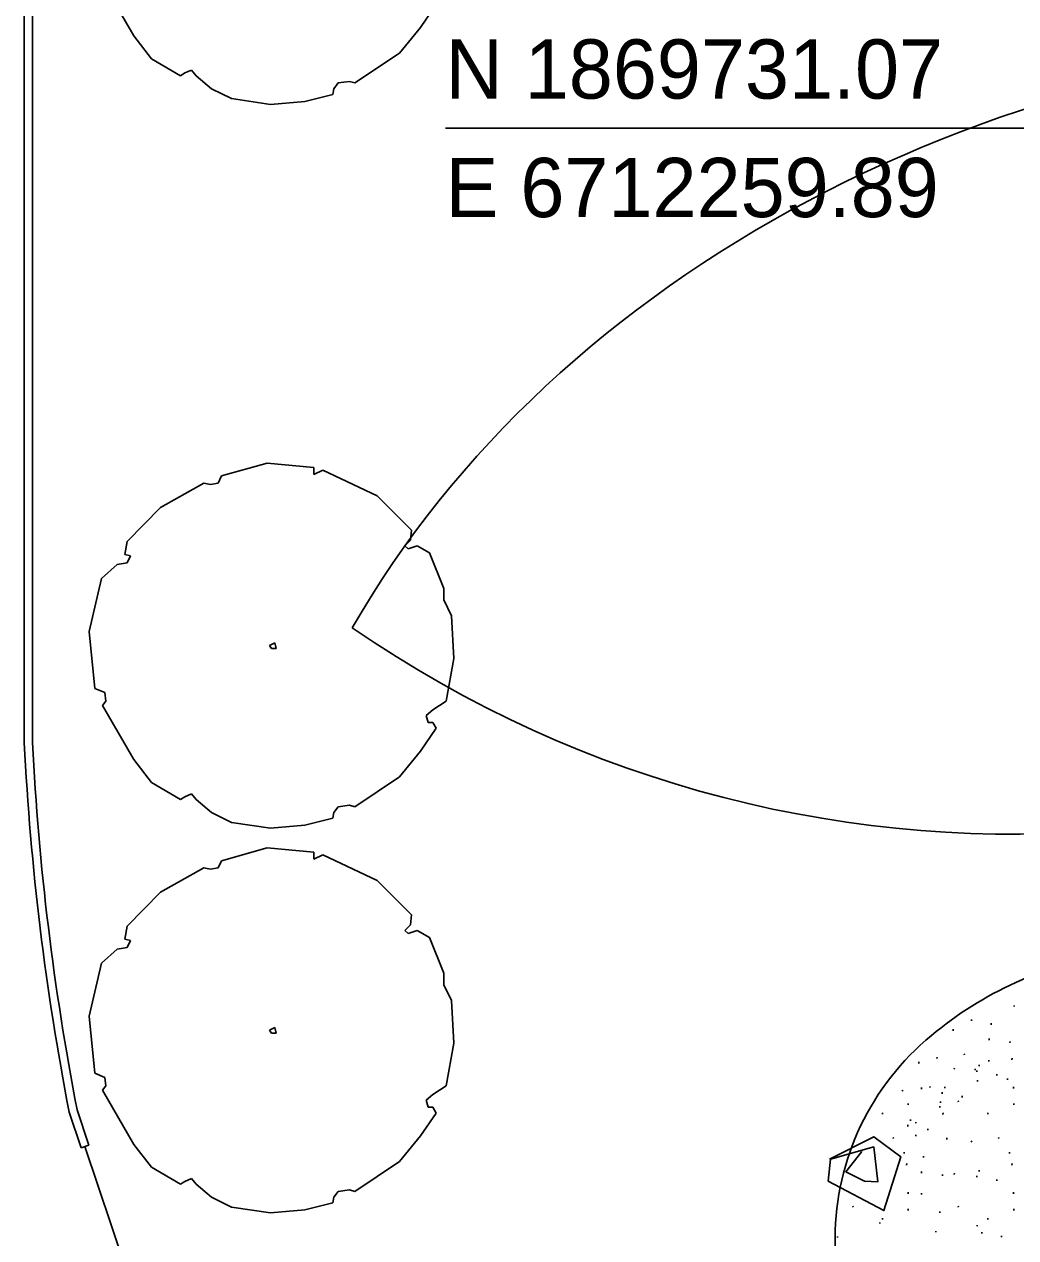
# Model space of a CAD drawing. Extents: x 6712138 to 6712574, y 1869536 to 1870160.
# Drawn here: x 6712188 to 6712248.3, y 1869628.3 to 1869702.1 of the extents above; entities that cross this region are included whole.
import ezdxf

# ---------------------------------------------------------------- set-up
doc = ezdxf.new("R2010")
doc.units = 0
for name, color, linetype in [('A-FLOR-PATT', 7, 'Continuous'), ('A-WALL', 7, 'Continuous'), ('C-PRKG-CONC', 7, 'Continuous'), ('I-WALL', 7, 'Continuous'), ('L-tree', 7, 'Continuous'), ('P-SANR-FIXT', 7, 'Continuous')]:
    doc.layers.add(name, color=color, linetype=linetype)

# ---------------------------------------------------------------- blocks, each defined once
blk = doc.blocks.new('TREE 1')
at = {"layer": 'L-tree'}
for p, q in [((-0.0275, 0.572), (-0.1682, 0.5324)), ((0.1167, 0.5588), (-0.0275, 0.572)), ((-0.1682, 0.5324), (-0.1785, 0.5104)), ((0.1167, 0.5368), (0.1167, 0.5588)), ((0.1441, 0.55), (0.1167, 0.5368)), ((0.3123, 0.4708), (0.1441, 0.55)), ((-0.2231, 0.5104), (-0.357, 0.4356)), ((-0.2025, 0.506), (-0.2231, 0.5104)), ((-0.1785, 0.5104), (-0.2025, 0.506)), ((0.4187, 0.3652), (0.3123, 0.4708)), ((-0.357, 0.4356), (-0.4599, 0.33)), ((0.4153, 0.3344), (0.4187, 0.3652)), ((-0.4599, 0.33), (-0.4668, 0.2904)), ((0.3981, 0.3168), (0.4153, 0.3344)), ((0.4084, 0.308), (0.3981, 0.3168)), ((0.4359, 0.3168), (0.4084, 0.308)), ((0.4737, 0.2948), (0.4359, 0.3168)), ((-0.4599, 0.264), (-0.4908, 0.2596)), ((-0.4668, 0.2904), (-0.4496, 0.286)), ((-0.4496, 0.286), (-0.4599, 0.264)), ((0.5183, 0.1848), (0.4737, 0.2948)), ((-0.4908, 0.2596), (-0.5389, 0.2156)), ((-0.5389, 0.2156), (-0.5766, 0.0528)), ((0.5183, 0.1496), (0.5183, 0.1848)), ((0.5423, 0.1012), (0.5183, 0.1496)), ((0.5492, -0.0308), (0.5423, 0.1012)), ((-0.5766, 0.0528), (-0.5595, -0.1232)), ((-0.0034, 0.0176), (-0.0206, 0.0088)), ((-0.0206, 0.0088), (-0.0137, 0)), ((-0.0137, 0), (0, 0)), ((0, 0), (-0.0034, 0.0176)), ((0.5251, -0.1628), (0.5492, -0.0308)), ((-0.5595, -0.1232), (-0.5286, -0.1364)), ((-0.5286, -0.1364), (-0.5251, -0.1628)), ((-0.5251, -0.1628), (-0.5354, -0.176)), ((-0.5354, -0.176), (-0.4393, -0.3432)), ((0.4839, -0.1892), (0.5251, -0.1628)), ((0.4634, -0.2068), (0.4839, -0.1892)), ((0.4702, -0.2288), (0.4634, -0.2068)), ((0.4462, -0.3168), (0.4942, -0.2464)), ((0.4839, -0.2288), (0.4702, -0.2288)), ((0.4942, -0.2464), (0.4839, -0.2288)), ((0.381, -0.396), (0.4462, -0.3168)), ((-0.4393, -0.3432), (-0.3844, -0.4136)), ((0.2437, -0.4884), (0.381, -0.396)), ((-0.3844, -0.4136), (-0.2952, -0.4664)), ((-0.2815, -0.4576), (-0.2609, -0.4488)), ((-0.2609, -0.4488), (-0.2471, -0.4664)), ((-0.2952, -0.4664), (-0.2815, -0.4576)), ((-0.2471, -0.4664), (-0.1991, -0.506)), ((0.1922, -0.4884), (0.2265, -0.484)), ((0.2265, -0.484), (0.2437, -0.4884)), ((-0.1991, -0.506), (-0.1373, -0.5368)), ((0.0892, -0.5456), (0.175, -0.5236)), ((0.175, -0.5236), (0.1785, -0.506)), ((0.1785, -0.506), (0.1922, -0.4884)), ((-0.1373, -0.5368), (-0.0172, -0.5544)), ((-0.0172, -0.5544), (0.0892, -0.5456))]:
    blk.add_line(p, q, dxfattribs=at)

msp = doc.modelspace()

# ---------------------------------------------------------------- linework, layer by layer
at = {"layer": 'A-FLOR-PATT'}
for p, q in [((6712248.165, 1869642.384), (6712248.165, 1869642.442)), ((6712245.574, 1869641.524), (6712245.574, 1869641.591)), ((6712246.762, 1869641.284), (6712246.762, 1869641.367)), ((6712244.464, 1869640.917), (6712244.464, 1869641.004)), ((6712246.642, 1869640.341), (6712246.642, 1869640.434)), ((6712247.902, 1869640.184), (6712247.911, 1869640.258)), ((6712242.372, 1869638.93), (6712242.372, 1869639.016)), ((6712243.453, 1869639.227), (6712243.49, 1869639.301)), ((6712245.147, 1869639.447), (6712245.12, 1869639.511)), ((6712246.628, 1869639.047), (6712246.628, 1869639.131)), ((6712248.016, 1869639.154), (6712248.033, 1869639.247)), ((6712244.519, 1869638.584), (6712244.527, 1869638.646)), ((6712245.784, 1869638.521), (6712245.784, 1869638.607)), ((6712245.889, 1869638.421), (6712245.889, 1869638.507)), ((6712246.042, 1869638.761), (6712246.042, 1869638.844)), ((6712247.102, 1869638.194), (6712247.102, 1869638.281)), ((6712242.525, 1869637.374), (6712242.525, 1869637.458)), ((6712243.055, 1869637.459), (6712243.028, 1869637.523)), ((6712243.95, 1869637.431), (6712243.95, 1869637.514)), ((6712245.924, 1869637.824), (6712245.94, 1869637.917)), ((6712247.748, 1869637.924), (6712247.748, 1869638.011)), ((6712248.125, 1869637.414), (6712248.125, 1869637.507)), ((6712241.361, 1869637.239), (6712241.398, 1869637.313)), ((6712243.796, 1869637.091), (6712243.796, 1869637.177)), ((6712245.01, 1869636.864), (6712245.01, 1869636.951)), ((6712241.729, 1869636.404), (6712241.729, 1869636.49)), ((6712243.645, 1869636.25), (6712243.645, 1869636.338)), ((6712243.692, 1869636.533), (6712243.692, 1869636.619)), ((6712244.785, 1869636.601), (6712244.756, 1869636.664)), ((6712248.133, 1869636.404), (6712248.133, 1869636.49)), ((6712240.152, 1869635.844), (6712240.152, 1869635.93)), ((6712241.858, 1869635.443), (6712241.858, 1869635.527)), ((6712242.189, 1869635.29), (6712242.189, 1869635.364)), ((6712243.832, 1869635.836), (6712243.848, 1869635.93)), ((6712246.556, 1869635.844), (6712246.556, 1869635.93)), ((6712241.704, 1869635.103), (6712241.704, 1869635.19)), ((6712242.189, 1869634.51), (6712242.189, 1869634.598)), ((6712242.918, 1869634.876), (6712242.918, 1869634.963)), ((6712240.835, 1869634.374), (6712240.809, 1869634.438)), ((6712244.062, 1869634.307), (6712244.062, 1869634.401)), ((6712245.545, 1869634.154), (6712245.582, 1869634.227)), ((6712247.239, 1869634.374), (6712247.213, 1869634.438)), ((6712241.472, 1869633.447), (6712241.472, 1869633.534)), ((6712242.659, 1869633.207), (6712242.659, 1869633.29)), ((6712247.876, 1869633.447), (6712247.876, 1869633.534)), ((6712241.612, 1869632.75), (6712241.629, 1869632.844)), ((6712242.539, 1869632.264), (6712242.539, 1869632.358)), ((6712246.042, 1869632.358), (6712246.042, 1869632.441)), ((6712248.016, 1869632.75), (6712248.033, 1869632.844)), ((6712243.799, 1869632.107), (6712243.809, 1869632.181)), ((6712244.519, 1869632.181), (6712244.529, 1869632.258)), ((6712245.889, 1869632.018), (6712245.889, 1869632.104)), ((6712247.102, 1869631.79), (6712247.102, 1869631.878)), ((6712241.721, 1869631.01), (6712241.721, 1869631.104)), ((6712242.525, 1869630.97), (6712242.525, 1869631.054)), ((6712248.125, 1869631.01), (6712248.125, 1869631.104)), ((6712238.381, 1869630.198), (6712238.352, 1869630.261)), ((6712241.729, 1869630.001), (6712241.729, 1869630.087)), ((6712244.785, 1869630.198), (6712244.756, 1869630.261)), ((6712248.133, 1869630.001), (6712248.133, 1869630.087)), ((6712240.152, 1869629.441), (6712240.152, 1869629.527)), ((6712243.645, 1869629.847), (6712243.645, 1869629.934)), ((6712246.556, 1869629.441), (6712246.556, 1869629.527)), ((6712240.006, 1869629.204), (6712240.006, 1869629.262)), ((6712243.405, 1869628.681), (6712243.405, 1869628.739)), ((6712245.916, 1869629.047), (6712245.916, 1869629.105)), ((6712246.202, 1869628.605), (6712246.202, 1869628.672)), ((6712237.415, 1869628.344), (6712237.415, 1869628.411)), ((6712247.389, 1869628.365), (6712247.389, 1869628.449))]:
    msp.add_line(p, q, dxfattribs=at)
at = {"layer": 'A-WALL'}
msp.add_lwpolyline([(6712237.276, 1869628.339), (6712237.274, 1869628.02), (6712237.289, 1869627.702)], dxfattribs=at)
for centre, radius, start, end in [((6712248.152, 1869723.615), 70.759, 235.35823, 315.03625), ((6712265.472, 1869606.31), 41.29, 104.71577, 114.63864), ((6712257.312, 1869623.731), 22.054, 114.23712, 130.01581), ((6712253.259, 1869628.256), 15.984, 129.31853, 179.70166)]:
    msp.add_arc(centre, radius, start, end, dxfattribs=at)
msp.add_ellipse((6712277.728, 1869639.009), major_axis=(77.005, 0), ratio=0.811403, start_param=1.592147, end_param=2.705522, dxfattribs=at)
at = {"layer": 'C-PRKG-CONC'}
for p, q in [((6712187.987, 1869658.415), (6712187.987, 1869784.192)), ((6712188.487, 1869658.428), (6712188.487, 1869784.192)), ((6712191.916, 1869633.968), (6712191.2, 1869636.102)), ((6712191.442, 1869633.809), (6712190.716, 1869635.974)), ((6712191.916, 1869633.968), (6712191.442, 1869633.809)), ((6712191.679, 1869633.888), (6712198.034, 1869614.925))]:
    msp.add_line(p, q, dxfattribs=at)
for radius, start, end in [(160.736, 182.89997, 190.96466), (160.236, 182.90449, 190.95285)]:
    msp.add_arc((6712348.517, 1869666.547), radius, start, end, dxfattribs=at)
at = {"layer": 'I-WALL'}
msp.add_lwpolyline([(6712254.345, 1869695.748), (6712213.597, 1869695.748)], dxfattribs=at)
at = {"layer": 'P-SANR-FIXT'}
msp.add_lwpolyline([(6712236.941, 1869633.103), (6712239.631, 1869634.471), (6712241.283, 1869633.245), (6712240.245, 1869629.99), (6712236.847, 1869631.783), (6712236.988, 1869633.103), (6712239.631, 1869633.858), (6712239.867, 1869631.735), (6712239.065, 1869631.783), (6712237.932, 1869632.349), (6712238.895, 1869633.587), (6712238.895, 1869633.587)], dxfattribs=at)

# ---------------------------------------------------------------- block references
at = {"layer": 'L-tree', "xscale": 19.685038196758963, "yscale": 19.685039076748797}
for p in [(6712203.293, 1869708.113), (6712203.293, 1869664.141), (6712203.293, 1869640.767)]:
    msp.add_blockref('TREE 1', p, dxfattribs=at)

# ---------------------------------------------------------------- texts
at = {"layer": 'I-WALL'}
for s, p in [('N 1869731.07', (6712213.597, 1869697.548)), ('E 6712259.89', (6712213.597, 1869690.348))]:
    msp.add_text(s, height=3.6, dxfattribs=at).set_placement(p)

doc.saveas('drawing.dxf')
